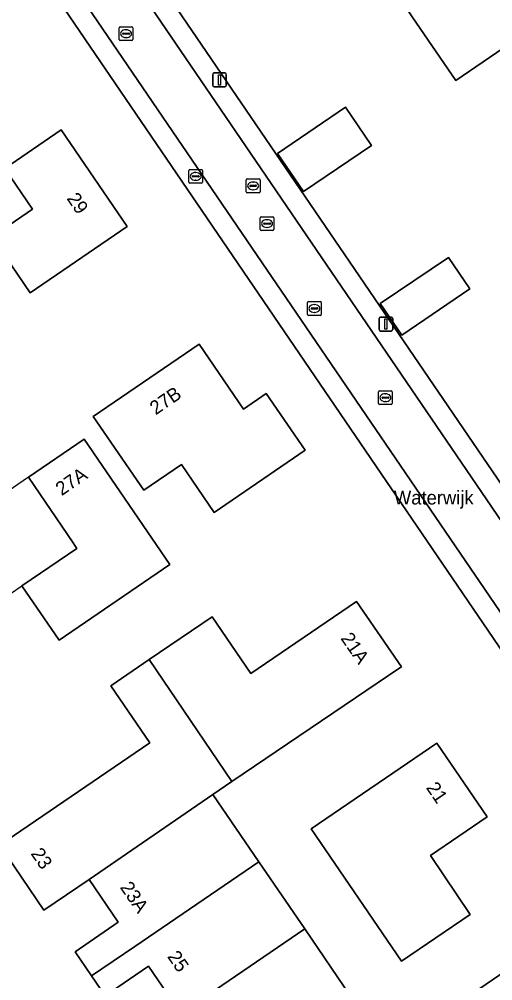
# Model space of a CAD drawing. Extents: x 155275 to 156265, y 382654 to 383635.
# Drawn here: x 155466.8 to 155501.2, y 383188.5 to 383258.3 of the extents above; entities that cross this region are included whole.
import ezdxf

# ---------------------------------------------------------------- set-up
doc = ezdxf.new("R2010")
doc.units = 0
for name, color, linetype in [('IMGEO_Brandkraan', 7, 'Continuous'), ('IMGEO_Erf', 7, 'Continuous'), ('IMGEO_Kolk', 7, 'Continuous'), ('IMGEO_Lichtmast', 7, 'Continuous'), ('IMGEO_Openbare_ruimte_label', 7, 'Continuous'), ('IMGEO_Pand', 7, 'Continuous'), ('IMGEO_Pand_nummerreeks', 7, 'Continuous'), ('IMGEO_Pand_overbouw', 7, 'Continuous'), ('IMGEO_Rijbaan_lokaal_open', 7, 'Continuous'), ('IMGEO_Rioolput', 7, 'Continuous'), ('IMGEO_Voetpad_open', 7, 'Continuous')]:
    doc.layers.add(name, color=color, linetype=linetype)

msp = doc.modelspace()

# ---------------------------------------------------------------- linework, layer by layer
at = {"layer": 'IMGEO_Brandkraan'}
for p, q in [((155479.084, 383246.486), (155479.084, 383247.338)), ((155479.159, 383247.412), (155480.011, 383247.412)), ((155479.343, 383246.906), (155479.343, 383246.918)), ((155479.386, 383246.955), (155479.784, 383246.955)), ((155479.572, 383247.192), (155479.597, 383247.192)), ((155479.827, 383246.918), (155479.827, 383246.906)), ((155480.085, 383247.338), (155480.085, 383246.486)), ((155480.011, 383246.412), (155479.159, 383246.412)), ((155479.781, 383246.869), (155479.383, 383246.869)), ((155479.595, 383246.632), (155479.57, 383246.632))]:
    msp.add_line(p, q, dxfattribs=at)
for points in [[(155479.084, 383246.486), (155479.084, 383247.338)], [(155479.159, 383247.412), (155480.011, 383247.412)], [(155480.085, 383247.338), (155480.085, 383246.486)], [(155480.011, 383246.412), (155479.159, 383246.412)]]:
    msp.add_lwpolyline(points, dxfattribs=at)
for centre, radius, start, end in [((155479.161, 383247.336), 0.0765, 91.55205, 178.44795), ((155479.161, 383247.336), 0.0765, 91.55205, 178.44795), ((155479.383, 383246.915), 0.0403, 85.87752, 175.75265), ((155479.788, 383246.917), 0.0386, 1.73085, 96.63898), ((155480.009, 383247.336), 0.0765, 1.55205, 88.44795), ((155480.009, 383247.336), 0.0765, 1.55205, 88.44795), ((155479.161, 383246.488), 0.0765, 181.55205, 268.44795), ((155479.161, 383246.488), 0.0765, 181.55205, 268.44795), ((155479.38, 383246.905), 0.0366, 178.93798, 274.71019), ((155479.784, 383246.912), 0.043, 264.86636, 352.45326), ((155480.009, 383246.488), 0.0765, 271.55205, 358.44795), ((155480.009, 383246.488), 0.0765, 271.55205, 358.44795)]:
    msp.add_arc(centre, radius, start, end, dxfattribs=at)
for centre, major_axis, ratio, start_param, end_param in [((155479.571, 383246.912), (-0.387, 0.002), 0.722429, 4.712389, 7.853982), ((155479.596, 383246.912), (-0.39, 0.002), 0.717154, 1.570796, 4.712389)]:
    msp.add_ellipse(centre, major_axis=major_axis, ratio=ratio, start_param=start_param, end_param=end_param, dxfattribs=at)
at = {"layer": 'IMGEO_Erf'}
for points in [[(155498.922, 383291.025), (155490.365, 383303.561), (155484.692, 383311.871), (155483.519, 383313.595), (155458.608, 383296.58), (155454.563, 383293.76), (155518.365, 383200.253), (155523.731, 383203.931), (155542.221, 383216.713), (155538.669, 383221.857), (155525.357, 383212.738), (155524.015, 383214.705), (155523.982, 383214.682), (155523.259, 383215.732), (155518.011, 383212.12), (155515.657, 383215.542), (155521.261, 383219.398), (155522.097, 383218.189), (155539.024, 383229.787), (155546.127, 383219.41), (155547.42, 383220.262)], [(155511.214, 383268.639), (155518.973, 383257.288), (155515.285, 383254.748), (155513.877, 383256.816), (155508.43, 383253.102), (155504.89, 383258.248), (155498.475, 383253.878), (155495.319, 383258.502), (155493.822, 383260.698), (155501.233, 383265.74), (155503.062, 383263.066)], [(155492.36, 383249.164), (155487.416, 383245.811), (155485.531, 383248.577), (155490.463, 383251.942)], [(155465.722, 383247.489), (155469.808, 383250.281), (155474.602, 383243.271), (155467.56, 383238.456), (155464.776, 383242.511), (155467.742, 383244.524)], [(155499.492, 383238.737), (155494.561, 383235.371), (155492.988, 383237.673), (155497.951, 383241.033)], [(155472.148, 383229.488), (155479.835, 383234.733), (155483.057, 383230.016), (155484.71, 383231.148), (155487.532, 383227.026), (155480.917, 383222.509), (155478.543, 383225.986), (155475.817, 383224.122)], [(155466.968, 383217.185), (155470.956, 383219.898), (155470.816, 383220.102), (155470.674, 383220.311), (155467.429, 383225.061), (155471.478, 383227.827), (155477.698, 383218.724), (155469.671, 383213.245)], [(155497.091, 383205.765), (155500.764, 383200.397), (155496.642, 383197.591), (155499.515, 383193.313), (155494.544, 383189.927), (155487.981, 383199.531)]]:
    msp.add_lwpolyline(points, close=True, dxfattribs=at)
for points in [[(155428.923, 383238.236), (155433.772, 383231.088), (155444.08, 383215.943), (155444.194, 383215.772), (155445.521, 383213.792), (155474.854, 383170.583), (155512.727, 383196.487), (155448.882, 383290.128), (155420.301, 383270.554)], [(155478.499, 383186.121), (155476.145, 383189.566), (155473.001, 383187.417), (155472.019, 383188.854), (155470.819, 383190.61), (155473.963, 383192.758), (155471.845, 383195.858), (155468.546, 383193.621), (155465.339, 383198.359), (155476.242, 383205.792), (155473.425, 383209.917), (155476.213, 383211.821), (155480.78, 383214.939), (155483.601, 383210.817), (155491.26, 383216.051), (155494.535, 383211.305), (155494.417, 383211.224), (155482.221, 383202.97), (155480.834, 383202.032), (155484.168, 383197.15), (155487.501, 383192.269), (155490.835, 383187.387)]]:
    msp.add_lwpolyline(points, dxfattribs=at)
at = {"layer": 'IMGEO_Kolk'}
for p, q in [((155484.268, 383243.057), (155484.268, 383243.909)), ((155484.343, 383243.983), (155485.195, 383243.983)), ((155484.527, 383243.477), (155484.527, 383243.489)), ((155484.965, 383243.44), (155484.567, 383243.44)), ((155484.57, 383243.526), (155484.968, 383243.526)), ((155484.756, 383243.763), (155484.781, 383243.763)), ((155485.011, 383243.489), (155485.011, 383243.477)), ((155485.269, 383243.909), (155485.269, 383243.057)), ((155485.195, 383242.983), (155484.343, 383242.983)), ((155484.779, 383243.203), (155484.754, 383243.203)), ((155492.863, 383230.418), (155492.863, 383231.27)), ((155492.938, 383231.344), (155493.79, 383231.344)), ((155493.165, 383230.887), (155493.563, 383230.887)), ((155493.351, 383231.124), (155493.376, 383231.124)), ((155493.864, 383231.27), (155493.864, 383230.418)), ((155493.79, 383230.344), (155492.938, 383230.344)), ((155493.122, 383230.838), (155493.122, 383230.85)), ((155493.56, 383230.801), (155493.162, 383230.801)), ((155493.374, 383230.564), (155493.349, 383230.564)), ((155493.606, 383230.85), (155493.606, 383230.838))]:
    msp.add_line(p, q, dxfattribs=at)
for points in [[(155484.268, 383243.057), (155484.268, 383243.909)], [(155484.343, 383243.983), (155485.195, 383243.983)], [(155485.269, 383243.909), (155485.269, 383243.057)], [(155485.195, 383242.983), (155484.343, 383242.983)], [(155492.863, 383230.418), (155492.863, 383231.27)], [(155492.938, 383231.344), (155493.79, 383231.344)], [(155493.864, 383231.27), (155493.864, 383230.418)], [(155493.79, 383230.344), (155492.938, 383230.344)]]:
    msp.add_lwpolyline(points, dxfattribs=at)
for centre, radius, start, end in [((155484.345, 383243.907), 0.0765, 91.55205, 178.44795), ((155484.345, 383243.907), 0.0765, 91.55205, 178.44795), ((155484.567, 383243.486), 0.0403, 85.87752, 175.75265), ((155484.564, 383243.476), 0.0366, 178.93798, 274.71019), ((155484.968, 383243.483), 0.043, 264.86636, 352.45326), ((155484.972, 383243.488), 0.0386, 1.73085, 96.63898), ((155485.193, 383243.907), 0.0765, 1.55205, 88.44795), ((155485.193, 383243.907), 0.0765, 1.55205, 88.44795), ((155484.345, 383243.059), 0.0765, 181.55205, 268.44795), ((155484.345, 383243.059), 0.0765, 181.55205, 268.44795), ((155485.193, 383243.059), 0.0765, 271.55205, 358.44795), ((155485.193, 383243.059), 0.0765, 271.55205, 358.44795), ((155492.94, 383231.268), 0.0765, 91.55205, 178.44795), ((155492.94, 383231.268), 0.0765, 91.55205, 178.44795), ((155493.162, 383230.847), 0.0403, 85.87752, 175.75265), ((155493.567, 383230.849), 0.0386, 1.73085, 96.63898), ((155493.788, 383231.268), 0.0765, 1.55205, 88.44795), ((155493.788, 383231.268), 0.0765, 1.55205, 88.44795), ((155492.94, 383230.42), 0.0765, 181.55205, 268.44795), ((155492.94, 383230.42), 0.0765, 181.55205, 268.44795), ((155493.159, 383230.837), 0.0366, 178.93798, 274.71019), ((155493.563, 383230.844), 0.043, 264.86636, 352.45326), ((155493.788, 383230.42), 0.0765, 271.55205, 358.44795), ((155493.788, 383230.42), 0.0765, 271.55205, 358.44795)]:
    msp.add_arc(centre, radius, start, end, dxfattribs=at)
for centre, major_axis, ratio, start_param, end_param in [((155484.755, 383243.483), (-0.387, 0.002), 0.722429, 4.712389, 7.853982), ((155484.78, 383243.483), (-0.39, 0.002), 0.717154, 1.570796, 4.712389), ((155493.35, 383230.844), (-0.387, 0.002), 0.722429, 4.712389, 7.853982), ((155493.375, 383230.844), (-0.39, 0.002), 0.717154, 1.570796, 4.712389)]:
    msp.add_ellipse(centre, major_axis=major_axis, ratio=ratio, start_param=start_param, end_param=end_param, dxfattribs=at)
at = {"layer": 'IMGEO_Lichtmast'}
for p, q in [((155480.82, 383253.519), (155480.82, 383254.319)), ((155480.82, 383254.319), (155480.82, 383253.519)), ((155480.92, 383254.419), (155481.71, 383254.419)), ((155481.71, 383254.419), (155480.92, 383254.419)), ((155481.81, 383254.319), (155481.81, 383253.519)), ((155481.81, 383253.519), (155481.81, 383254.319)), ((155481.71, 383253.419), (155480.92, 383253.419)), ((155480.92, 383253.419), (155481.71, 383253.419)), ((155492.906, 383235.784), (155492.906, 383236.584)), ((155492.906, 383236.584), (155492.906, 383235.784)), ((155493.006, 383236.684), (155493.796, 383236.684)), ((155493.796, 383236.684), (155493.006, 383236.684)), ((155493.896, 383236.584), (155493.896, 383235.784)), ((155493.896, 383235.784), (155493.896, 383236.584)), ((155493.796, 383235.684), (155493.006, 383235.684)), ((155493.006, 383235.684), (155493.796, 383235.684))]:
    msp.add_line(p, q, dxfattribs=at)
for points in [[(155481.24, 383254.294), (155481.39, 383254.294), (155481.39, 383253.544), (155481.24, 383253.544), (155481.24, 383254.294)], [(155493.326, 383236.559), (155493.476, 383236.559), (155493.476, 383235.809), (155493.326, 383235.809), (155493.326, 383236.559)]]:
    msp.add_lwpolyline(points, dxfattribs=at)
for centre, start, end in [((155480.92, 383254.319), 90, 180), ((155480.92, 383254.319), 90, 180), ((155481.71, 383254.319), 0, 90), ((155481.71, 383254.319), 360, 90), ((155480.92, 383253.519), 180, 270), ((155480.92, 383253.519), 180, 270), ((155481.71, 383253.519), 270, 0), ((155481.71, 383253.519), 270, 0), ((155493.006, 383236.584), 90, 180), ((155493.006, 383236.584), 90, 180), ((155493.796, 383236.584), 0, 90), ((155493.796, 383236.584), 360, 90), ((155493.006, 383235.784), 180, 270), ((155493.006, 383235.784), 180, 270), ((155493.796, 383235.784), 270, 0), ((155493.796, 383235.784), 270, 0)]:
    msp.add_arc(centre, 0.1, start, end, dxfattribs=at)
at = {"layer": 'IMGEO_Pand'}
for points in [[(155511.214, 383268.639), (155503.062, 383263.066), (155501.233, 383265.74), (155493.822, 383260.698), (155495.319, 383258.502), (155498.475, 383253.878), (155504.89, 383258.248), (155508.43, 383253.102), (155513.877, 383256.816), (155515.285, 383254.748), (155518.973, 383257.288)], [(155487.416, 383245.811), (155492.36, 383249.164), (155490.463, 383251.942), (155485.531, 383248.577)], [(155469.808, 383250.281), (155465.722, 383247.489), (155467.742, 383244.524), (155464.776, 383242.511), (155467.56, 383238.456), (155474.602, 383243.271)], [(155499.492, 383238.737), (155497.951, 383241.033), (155492.988, 383237.673), (155494.561, 383235.371)], [(155484.71, 383231.148), (155483.057, 383230.016), (155479.835, 383234.733), (155472.148, 383229.488), (155475.817, 383224.122), (155478.543, 383225.986), (155480.917, 383222.509), (155487.532, 383227.026)], [(155471.478, 383227.827), (155467.429, 383225.061), (155470.674, 383220.311), (155470.816, 383220.102), (155470.956, 383219.898), (155466.968, 383217.185), (155469.671, 383213.245), (155477.698, 383218.724)], [(155494.535, 383211.305), (155491.26, 383216.051), (155483.601, 383210.817), (155480.78, 383214.939), (155476.213, 383211.821), (155482.221, 383202.97), (155494.417, 383211.224)], [(155480.834, 383202.032), (155482.221, 383202.97), (155476.213, 383211.821), (155473.425, 383209.917), (155476.242, 383205.792), (155465.339, 383198.359), (155468.546, 383193.621), (155471.845, 383195.858)], [(155497.091, 383205.765), (155487.981, 383199.531), (155494.544, 383189.927), (155499.515, 383193.313), (155496.642, 383197.591), (155500.764, 383200.397)], [(155484.168, 383197.15), (155480.834, 383202.032), (155471.845, 383195.858), (155473.963, 383192.758), (155470.819, 383190.61), (155472.019, 383188.854), (155475.164, 383191.002)], [(155487.501, 383192.269), (155484.168, 383197.15), (155475.164, 383191.002), (155472.019, 383188.854), (155473.001, 383187.417), (155476.145, 383189.566), (155478.499, 383186.121)], [(155487.501, 383192.269), (155478.499, 383186.121), (155480.496, 383183.2), (155477.183, 383180.953), (155479.766, 383177.154), (155487.313, 383182.306), (155486.07, 383184.133), (155490.835, 383187.387)]]:
    msp.add_lwpolyline(points, close=True, dxfattribs=at)
at = {"layer": 'IMGEO_Pand_overbouw'}
msp.add_lwpolyline([(155462.597, 383221.76), (155466.121, 383216.608), (155466.968, 383217.185), (155470.956, 383219.898), (155470.816, 383220.102), (155470.674, 383220.311), (155467.429, 383225.061)], close=True, dxfattribs=at)
at = {"layer": 'IMGEO_Rijbaan_lokaal_open'}
for points in [[(155448.903, 383292.685), (155450.079, 383290.961), (155513.95, 383197.324), (155515.231, 383195.446)], [(155518.343, 383197.603), (155517.119, 383199.399), (155453.361, 383292.898)]]:
    msp.add_lwpolyline(points, dxfattribs=at)
at = {"layer": 'IMGEO_Rioolput'}
for p, q in [((155474.023, 383256.848), (155474.023, 383257.7)), ((155474.098, 383257.774), (155474.95, 383257.774)), ((155474.511, 383257.554), (155474.536, 383257.554)), ((155475.024, 383257.7), (155475.024, 383256.848)), ((155474.95, 383256.774), (155474.098, 383256.774)), ((155474.282, 383257.268), (155474.282, 383257.28)), ((155474.72, 383257.231), (155474.322, 383257.231)), ((155474.325, 383257.317), (155474.723, 383257.317)), ((155474.534, 383256.994), (155474.509, 383256.994)), ((155474.766, 383257.28), (155474.766, 383257.268)), ((155483.26, 383245.797), (155483.26, 383246.649)), ((155483.335, 383246.723), (155484.187, 383246.723)), ((155483.519, 383246.217), (155483.519, 383246.229)), ((155483.562, 383246.266), (155483.96, 383246.266)), ((155483.748, 383246.503), (155483.773, 383246.503)), ((155484.003, 383246.229), (155484.003, 383246.217)), ((155484.261, 383246.649), (155484.261, 383245.797)), ((155484.187, 383245.723), (155483.335, 383245.723)), ((155483.957, 383246.18), (155483.559, 383246.18)), ((155483.771, 383245.943), (155483.746, 383245.943)), ((155487.708, 383236.893), (155487.708, 383237.745)), ((155487.783, 383237.819), (155488.635, 383237.819)), ((155487.967, 383237.313), (155487.967, 383237.325)), ((155488.405, 383237.276), (155488.007, 383237.276)), ((155488.01, 383237.362), (155488.408, 383237.362)), ((155488.196, 383237.599), (155488.221, 383237.599)), ((155488.451, 383237.325), (155488.451, 383237.313)), ((155488.709, 383237.745), (155488.709, 383236.893)), ((155488.635, 383236.819), (155487.783, 383236.819)), ((155488.219, 383237.039), (155488.194, 383237.039))]:
    msp.add_line(p, q, dxfattribs=at)
for points in [[(155474.023, 383256.848), (155474.023, 383257.7)], [(155474.098, 383257.774), (155474.95, 383257.774)], [(155475.024, 383257.7), (155475.024, 383256.848)], [(155474.95, 383256.774), (155474.098, 383256.774)], [(155483.26, 383245.797), (155483.26, 383246.649)], [(155483.335, 383246.723), (155484.187, 383246.723)], [(155484.261, 383246.649), (155484.261, 383245.797)], [(155484.187, 383245.723), (155483.335, 383245.723)], [(155487.708, 383236.893), (155487.708, 383237.745)], [(155487.783, 383237.819), (155488.635, 383237.819)], [(155488.709, 383237.745), (155488.709, 383236.893)], [(155488.635, 383236.819), (155487.783, 383236.819)]]:
    msp.add_lwpolyline(points, dxfattribs=at)
for centre, radius, start, end in [((155474.1, 383257.698), 0.0765, 91.55205, 178.44795), ((155474.1, 383257.698), 0.0765, 91.55205, 178.44795), ((155474.948, 383257.698), 0.0765, 1.55205, 88.44795), ((155474.948, 383257.698), 0.0765, 1.55205, 88.44795), ((155474.1, 383256.85), 0.0765, 181.55205, 268.44795), ((155474.1, 383256.85), 0.0765, 181.55205, 268.44795), ((155474.322, 383257.277), 0.0403, 85.87752, 175.75265), ((155474.319, 383257.267), 0.0366, 178.93798, 274.71019), ((155474.723, 383257.274), 0.043, 264.86636, 352.45326), ((155474.727, 383257.279), 0.0386, 1.73085, 96.63898), ((155474.948, 383256.85), 0.0765, 271.55205, 358.44795), ((155474.948, 383256.85), 0.0765, 271.55205, 358.44795), ((155483.337, 383246.647), 0.0765, 91.55205, 178.44795), ((155483.337, 383246.647), 0.0765, 91.55205, 178.44795), ((155483.559, 383246.226), 0.0403, 85.87752, 175.75265), ((155483.556, 383246.216), 0.0366, 178.93798, 274.71019), ((155483.96, 383246.223), 0.043, 264.86636, 352.45326), ((155483.964, 383246.228), 0.0386, 1.73085, 96.63898), ((155484.185, 383246.647), 0.0765, 1.55205, 88.44795), ((155484.185, 383246.647), 0.0765, 1.55205, 88.44795), ((155483.337, 383245.799), 0.0765, 181.55205, 268.44795), ((155483.337, 383245.799), 0.0765, 181.55205, 268.44795), ((155484.185, 383245.799), 0.0765, 271.55205, 358.44795), ((155484.185, 383245.799), 0.0765, 271.55205, 358.44795), ((155487.785, 383237.743), 0.0765, 91.55205, 178.44795), ((155487.785, 383237.743), 0.0765, 91.55205, 178.44795), ((155488.007, 383237.322), 0.0403, 85.87752, 175.75265), ((155488.004, 383237.312), 0.0366, 178.93798, 274.71019), ((155488.408, 383237.319), 0.043, 264.86636, 352.45326), ((155488.412, 383237.324), 0.0386, 1.73085, 96.63898), ((155488.633, 383237.743), 0.0765, 1.55205, 88.44795), ((155488.633, 383237.743), 0.0765, 1.55205, 88.44795), ((155487.785, 383236.895), 0.0765, 181.55205, 268.44795), ((155487.785, 383236.895), 0.0765, 181.55205, 268.44795), ((155488.633, 383236.895), 0.0765, 271.55205, 358.44795), ((155488.633, 383236.895), 0.0765, 271.55205, 358.44795)]:
    msp.add_arc(centre, radius, start, end, dxfattribs=at)
for centre, major_axis, ratio, start_param, end_param in [((155474.51, 383257.274), (-0.387, 0.002), 0.722429, 4.712389, 7.853982), ((155474.535, 383257.274), (-0.39, 0.002), 0.717154, 1.570796, 4.712389), ((155483.747, 383246.223), (-0.387, 0.002), 0.722429, 4.712389, 7.853982), ((155483.772, 383246.223), (-0.39, 0.002), 0.717154, 1.570796, 4.712389), ((155488.195, 383237.319), (-0.387, 0.002), 0.722429, 4.712389, 7.853982), ((155488.22, 383237.319), (-0.39, 0.002), 0.717154, 1.570796, 4.712389)]:
    msp.add_ellipse(centre, major_axis=major_axis, ratio=ratio, start_param=start_param, end_param=end_param, dxfattribs=at)
at = {"layer": 'IMGEO_Voetpad_open'}
for points in [[(155454.563, 383293.76), (155453.361, 383292.898), (155517.119, 383199.399), (155518.365, 383200.253)], [(155450.079, 383290.961), (155448.882, 383290.128), (155512.727, 383196.487), (155513.95, 383197.324)]]:
    msp.add_lwpolyline(points, close=True, dxfattribs=at)
msp.add_lwpolyline([(155515.231, 383195.446), (155513.95, 383197.324), (155512.727, 383196.487), (155474.854, 383170.583), (155476.977, 383167.454), (155478.425, 383165.321), (155478.515, 383165.379), (155480.355, 383166.638), (155479.896, 383167.306), (155477.463, 383170.842), (155482.819, 383174.511), (155484.874, 383175.918), (155489.868, 383179.279), (155493.989, 383182.14), (155502.958, 383188.287), (155507.151, 383191.154), (155513.423, 383195.446), (155514.167, 383194.371)], dxfattribs=at)

# ---------------------------------------------------------------- texts
at = {"layer": 'IMGEO_Openbare_ruimte_label'}
msp.add_text('Waterwijk', height=1, dxfattribs=at).set_placement((155493.98, 383223.087))
at = {"layer": 'IMGEO_Pand_nummerreeks'}
for s, rotation, p in [('29', 304.3658, (155470.183, 383245.304)), ('27B', 34.30871, (155476.683, 383229.556)), ('27A', 34.33736, (155469.848, 383223.686)), ('21A', 304.60644, (155490.076, 383213.365)), ('21', 304.38299, (155496.286, 383202.515)), ('23', 304.09078, (155467.572, 383197.736)), ('23A', 304.34861, (155474.052, 383195.288)), ('25', 304.34861, (155477.488, 383190.259))]:
    msp.add_text(s, height=1, rotation=rotation, dxfattribs=at).set_placement(p)

doc.saveas('drawing.dxf')
